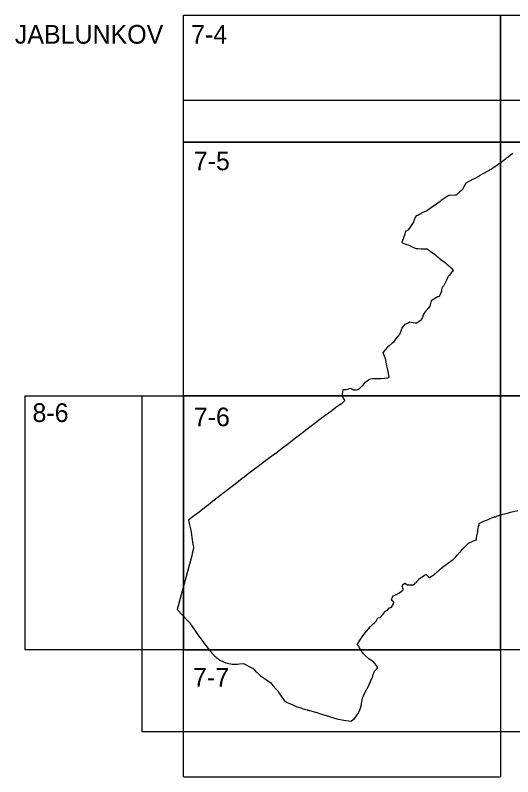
# Model space of a CAD drawing. Extents: x -447352 to -425530, y -1135906 to -1125104.
# Drawn here: x -441800.2 to -441555.1, y -1126653.4 to -1126278.4 of the extents above; entities that cross this region are included whole.
import ezdxf

# ---------------------------------------------------------------- set-up
doc = ezdxf.new("R2010")
doc.units = 0
for name, color, linetype in [('Vrstva 1', 7, 'Continuous'), ('Vrstva 10', 7, 'Continuous'), ('Vrstva 4', 7, 'Continuous')]:
    doc.layers.add(name, color=color, linetype=linetype)

msp = doc.modelspace()

# ---------------------------------------------------------------- linework, layer by layer
at = {"layer": 'Vrstva 1'}
for points in [[(-441555.05, -1126346.44), (-441556.26, -1126347.4), (-441556.26, -1126347.4), (-441557.41, -1126348.27), (-441557.98, -1126348.7), (-441558.56, -1126349.14), (-441558.72, -1126349.26), (-441560.85, -1126350.9), (-441561.92, -1126351.72), (-441562.39, -1126352.06), (-441563.15, -1126352.57), (-441563.4, -1126352.73), (-441563.99, -1126353.12), (-441564.03, -1126353.15), (-441564.24, -1126353.29), (-441565.15, -1126353.89), (-441565.16, -1126353.89), (-441565.63, -1126354.15), (-441565.78, -1126354.23), (-441565.96, -1126354.33), (-441566.42, -1126354.58), (-441566.6, -1126354.69), (-441566.76, -1126354.78), (-441566.86, -1126354.84), (-441567.1, -1126354.98), (-441568.76, -1126355.92), (-441568.93, -1126356.01), (-441569.16, -1126356.14), (-441571.63, -1126357.54), (-441571.75, -1126357.61), (-441573.86, -1126358.74), (-441574.88, -1126359.29), (-441578.22, -1126361.1), (-441578.39, -1126361.4), (-441578.45, -1126361.51), (-441579.23, -1126362.97), (-441579.91, -1126364.29), (-441580.05, -1126364.42), (-441580.14, -1126364.5), (-441581.28, -1126365.54), (-441582.79, -1126366.92), (-441582.96, -1126367.07), (-441582.96, -1126367.08), (-441583.43, -1126367.09), (-441586.62, -1126367.18), (-441586.63, -1126367.18), (-441587.06, -1126367.47), (-441587.89, -1126368.04), (-441590.36, -1126369.7), (-441590.4, -1126369.72), (-441590.64, -1126369.9), (-441590.91, -1126370.1), (-441593.89, -1126372.23), (-441593.96, -1126372.28), (-441596.96, -1126374.46), (-441597.43, -1126374.8), (-441597.59, -1126374.86), (-441599.53, -1126375.58), (-441599.54, -1126375.58), (-441599.93, -1126375.82), (-441601.81, -1126376.98), (-441602.73, -1126377.19), (-441602.98, -1126377.7), (-441603.74, -1126379.21), (-441603.75, -1126379.22), (-441603.82, -1126379.48), (-441604.02, -1126380.32), (-441604.85, -1126381.43), (-441606.22, -1126383.38), (-441606.78, -1126384.19), (-441606.81, -1126384.21), (-441607.97, -1126384.85), (-441608.07, -1126384.91), (-441608.14, -1126385.3), (-441608.29, -1126386.11), (-441608.34, -1126386.3), (-441609.63, -1126389.88), (-441609.8, -1126390.36), (-441609.77, -1126390.35), (-441609.75, -1126390.34), (-441609.07, -1126390.6), (-441607.26, -1126391.26), (-441606.64, -1126391.55), (-441604.35, -1126392.63), (-441604.33, -1126392.63), (-441603.17, -1126393.1), (-441602.7, -1126393.28), (-441602.67, -1126393.29), (-441602.24, -1126393.32), (-441602.1, -1126393.33), (-441601.88, -1126393.35), (-441600.28, -1126393.45), (-441599.24, -1126393.52), (-441598.19, -1126393.49), (-441597.35, -1126393.46), (-441597.34, -1126393.46), (-441597.06, -1126393.61), (-441596.69, -1126393.87), (-441596.14, -1126394.25), (-441595.75, -1126394.53), (-441594.19, -1126395.67), (-441594.02, -1126395.79), (-441592.91, -1126396.71), (-441592.52, -1126397.03), (-441592.34, -1126397.18), (-441591.59, -1126397.79), (-441591.32, -1126398.02), (-441590.72, -1126398.51), (-441590.5, -1126398.69), (-441589.86, -1126399.11), (-441589.11, -1126399.61), (-441589.08, -1126399.63), (-441588.32, -1126400.31), (-441587.44, -1126401.09), (-441587, -1126401.47), (-441585.99, -1126402.36), (-441585.73, -1126402.59), (-441585.68, -1126402.64), (-441585.58, -1126402.74), (-441585.57, -1126402.75), (-441585.48, -1126402.85), (-441585.45, -1126402.88), (-441584.4, -1126404.11), (-441584.41, -1126404.12), (-441584.85, -1126404.61), (-441584.91, -1126404.68), (-441585.48, -1126405.31), (-441586.3, -1126406.37), (-441586.47, -1126406.58), (-441587.03, -1126407.3), (-441587.33, -1126407.83), (-441587.35, -1126407.87), (-441587.36, -1126407.89), (-441587.49, -1126408.17), (-441588.29, -1126409.84), (-441588.6, -1126410.48), (-441589.22, -1126411.77), (-441589.33, -1126412.01), (-441589.34, -1126412.01), (-441589.38, -1126412.04), (-441589.67, -1126412.24), (-441589.75, -1126412.28), (-441589.8, -1126412.38), (-441589.89, -1126412.58), (-441589.98, -1126412.86), (-441590.15, -1126413.42), (-441590.16, -1126413.44), (-441590.28, -1126413.94), (-441590.3, -1126414.01), (-441590.29, -1126414.07), (-441590.28, -1126414.15), (-441590.28, -1126414.22), (-441590.29, -1126414.27), (-441591.17, -1126416.6), (-441591.19, -1126416.65), (-441591.21, -1126416.69), (-441591.22, -1126416.7), (-441591.92, -1126417), (-441592.17, -1126417.11), (-441592.64, -1126417.35), (-441595.25, -1126419.04), (-441595.25, -1126419.04), (-441595.62, -1126420.35), (-441595.7, -1126420.61), (-441595.81, -1126421.03), (-441595.87, -1126421.24), (-441595.87, -1126421.25), (-441595.86, -1126421.25), (-441595.69, -1126421.41), (-441595.7, -1126421.42), (-441596.06, -1126421.81), (-441596.86, -1126422.81), (-441596.87, -1126422.82), (-441597.08, -1126423.07), (-441597.08, -1126423.08), (-441597.2, -1126423.23), (-441598.36, -1126424.58), (-441598.9, -1126425.21), (-441599.66, -1126427.16), (-441600.04, -1126428.18), (-441600.17, -1126428.53), (-441601.7, -1126429.63), (-441602.32, -1126430.07), (-441602.5, -1126430.11), (-441602.52, -1126430.11), (-441603.15, -1126430.02), (-441605.99, -1126429.6), (-441606.48, -1126429.84), (-441607.81, -1126430.48), (-441608.35, -1126430.74), (-441608.38, -1126430.77), (-441608.81, -1126431.18), (-441608.98, -1126431.4), (-441609.64, -1126432.25), (-441609.64, -1126432.26), (-441610.31, -1126434.06), (-441610.88, -1126435.56), (-441610.88, -1126435.56), (-441611.02, -1126435.78), (-441611.35, -1126436.15), (-441612.07, -1126436.95), (-441612.77, -1126437.72), (-441612.78, -1126437.74), (-441612.91, -1126437.93), (-441613.98, -1126439.5), (-441614.45, -1126439.88), (-441616.02, -1126441.14), (-441616.69, -1126441.68), (-441616.79, -1126441.76), (-441616.82, -1126441.8), (-441617.94, -1126443.23), (-441619.08, -1126444.54), (-441618.93, -1126444.71), (-441618.92, -1126444.74), (-441618.92, -1126444.75), (-441617.91, -1126447.51), (-441617.63, -1126449.17), (-441617.31, -1126451.12), (-441616.9, -1126453.08), (-441616.17, -1126456.58), (-441616.13, -1126456.78), (-441616.78, -1126457.12), (-441616.9, -1126457.19), (-441620.07, -1126457.45), (-441620.23, -1126457.45), (-441621.72, -1126457.42), (-441624.11, -1126457.4), (-441625.39, -1126457.67), (-441625.99, -1126457.94), (-441626.97, -1126458.74), (-441628.27, -1126459.61), (-441628.36, -1126459.72), (-441629.52, -1126461.14), (-441630.97, -1126462.48), (-441631.66, -1126462.8), (-441632.26, -1126463.08), (-441633.43, -1126463.01), (-441635.04, -1126462.16), (-441637.28, -1126462.83), (-441638.76, -1126462.8), (-441639.14, -1126464.91), (-441639.15, -1126464.93), (-441639.16, -1126465.02), (-441638.87, -1126466.83), (-441637.9, -1126468.15), (-441637.89, -1126468.17), (-441638.63, -1126468.92), (-441639.24, -1126469.48), (-441639.49, -1126469.71), (-441640.29, -1126470.34), (-441642.22, -1126471.57), (-441642.28, -1126471.61), (-441644.25, -1126473.14), (-441644.31, -1126473.18), (-441644.8, -1126473.56), (-441649.46, -1126477.02), (-441649.49, -1126477.05), (-441654.44, -1126480.81), (-441658.7, -1126484.06), (-441659.58, -1126484.72), (-441662.15, -1126486.66), (-441666.15, -1126489.79), (-441668.59, -1126491.66), (-441671.9, -1126494.19), (-441671.95, -1126494.23), (-441676.74, -1126497.74), (-441676.97, -1126497.92), (-441680.58, -1126500.6), (-441682.97, -1126502.42), (-441684.94, -1126503.9), (-441687.26, -1126505.65), (-441687.49, -1126505.82), (-441688.62, -1126506.71), (-441693.44, -1126510.51), (-441697.33, -1126513.46), (-441701.55, -1126516.71), (-441702.84, -1126517.71), (-441705.23, -1126519.59), (-441706.41, -1126520.51), (-441710.35, -1126523.56), (-441711.28, -1126524.27), (-441712.52, -1126525.23), (-441714.84, -1126527.03), (-441714.84, -1126527.03), (-441714.8, -1126527.21), (-441714.51, -1126528.59), (-441714.48, -1126528.75), (-441713.95, -1126531.29), (-441713.79, -1126532.02), (-441713.79, -1126532.06), (-441712.86, -1126537.94), (-441712.85, -1126537.97), (-441712.55, -1126539.7), (-441712.55, -1126539.72), (-441712.49, -1126540.09), (-441712.43, -1126540.51), (-441712.46, -1126540.88), (-441712.61, -1126541.61), (-441712.99, -1126543.4), (-441713.28, -1126544.58), (-441713.3, -1126544.63), (-441714.41, -1126548.8), (-441716.51, -1126556.68), (-441718.5, -1126563.9), (-441720.43, -1126571), (-441720.44, -1126571.04), (-441715.16, -1126576.64), (-441714.11, -1126577.77), (-441713.35, -1126578.99), (-441711.33, -1126582.05), (-441711.28, -1126582.12), (-441710.27, -1126583.53), (-441710.11, -1126583.74), (-441708.23, -1126586.22), (-441707.66, -1126586.96), (-441707.63, -1126587), (-441707.11, -1126587.72), (-441705.73, -1126589.62), (-441705.4, -1126590.07), (-441703.25, -1126592.79), (-441701.85, -1126594.01), (-441699.45, -1126595.99), (-441697.71, -1126596.74), (-441696.52, -1126597.26), (-441696.39, -1126597.31), (-441695.06, -1126597.59), (-441694.92, -1126597.62), (-441693.3, -1126597.95), (-441693.27, -1126597.95), (-441692.31, -1126597.93), (-441691.93, -1126597.93), (-441691.41, -1126597.92), (-441690.73, -1126597.91), (-441689.82, -1126597.87), (-441687.87, -1126597.71), (-441687.42, -1126597.78), (-441686.76, -1126598.13), (-441685.04, -1126599.08), (-441683.08, -1126600.18), (-441682.56, -1126600.66), (-441681.84, -1126601.34), (-441681.04, -1126602.09), (-441679.72, -1126603.39), (-441679.58, -1126603.49), (-441678.39, -1126604.34), (-441675.98, -1126606.05), (-441674.34, -1126607.23), (-441673.29, -1126608.41), (-441671.65, -1126610.23), (-441671.01, -1126610.94), (-441670.65, -1126611.53), (-441670.19, -1126612.27), (-441669.25, -1126613.74), (-441668.62, -1126614.66), (-441667.58, -1126616.1), (-441666.51, -1126616.61), (-441665.13, -1126617.26), (-441663.82, -1126617.87), (-441661.85, -1126618.76), (-441660.72, -1126619.11), (-441659, -1126619.68), (-441658.85, -1126619.73), (-441657.76, -1126620.05), (-441656.34, -1126620.47), (-441656.33, -1126620.47), (-441656.12, -1126620.53), (-441656.06, -1126620.55), (-441655.2, -1126620.81), (-441652.81, -1126621.5), (-441652.69, -1126621.54), (-441652.21, -1126621.68), (-441649.28, -1126622.55), (-441646.59, -1126623.38), (-441646.25, -1126623.48), (-441645.49, -1126623.71), (-441643.48, -1126624.33), (-441641.75, -1126624.88), (-441638.29, -1126625.62)], [(-441638.29, -1126625.62), (-441635.9, -1126625.81), (-441634.7, -1126626.04), (-441634.59, -1126625.95), (-441633.01, -1126624.68), (-441631.98, -1126623.2), (-441631.87, -1126623.05), (-441631.35, -1126622.29), (-441631.24, -1126622.12), (-441631.1, -1126621.89), (-441630.72, -1126621.26), (-441630.45, -1126620.43), (-441630.43, -1126620.36), (-441630.41, -1126620.31), (-441630.38, -1126620.2), (-441630.35, -1126620.11), (-441630.35, -1126620.1), (-441629.72, -1126617.9), (-441629.58, -1126617.38), (-441629.13, -1126614.63), (-441629.13, -1126614.63), (-441628.94, -1126614.19), (-441628.68, -1126613.57), (-441627.89, -1126611.74), (-441626.32, -1126609.09), (-441624.57, -1126604.96), (-441624.25, -1126604.32), (-441624.21, -1126604.19), (-441623.82, -1126603.09), (-441623.23, -1126601.42), (-441621.55, -1126599.71), (-441622.48, -1126598.47), (-441622.54, -1126598.38), (-441622.59, -1126598.32), (-441622.62, -1126598.28), (-441622.69, -1126598.18), (-441622.74, -1126598.1), (-441622.82, -1126597.98), (-441623.18, -1126597.46), (-441623.55, -1126597), (-441624.12, -1126596.63), (-441624.22, -1126596.57), (-441625.87, -1126595.5), (-441628.06, -1126593.56), (-441628.19, -1126593.39), (-441628.22, -1126593.35), (-441628.3, -1126593.25), (-441628.64, -1126592.83), (-441628.97, -1126592.42), (-441629.23, -1126592.1), (-441629.71, -1126591.51), (-441629.79, -1126591.41), (-441630.29, -1126590.45), (-441630.58, -1126589.89), (-441630.81, -1126589.46), (-441630.86, -1126589.37), (-441630.9, -1126589.32), (-441631.16, -1126589.03), (-441631.36, -1126588.8), (-441631.62, -1126588.51), (-441631.84, -1126588.26), (-441629.98, -1126585.52), (-441629.89, -1126585.4), (-441629.57, -1126584.95), (-441629.25, -1126584.51), (-441627.92, -1126582.68), (-441625.24, -1126579.42), (-441624.89, -1126579.1), (-441624.18, -1126578.4), (-441624.07, -1126578.31), (-441623.88, -1126578.17), (-441623.28, -1126577.69), (-441622.42, -1126576.85), (-441622.01, -1126576.09), (-441621.54, -1126575.22), (-441620.49, -1126574.98), (-441619.09, -1126573.55), (-441618.55, -1126572.7), (-441618.54, -1126572.69), (-441618.54, -1126572.67), (-441618.33, -1126572.34), (-441618.28, -1126572.26), (-441618.04, -1126571.87), (-441616.88, -1126571.43), (-441615.86, -1126570.25), (-441615.33, -1126570.05), (-441615.21, -1126570), (-441614.79, -1126569.84), (-441614.57, -1126569.45), (-441614.52, -1126569.36), (-441614.35, -1126569.06), (-441613.94, -1126568.32), (-441613.74, -1126567.41), (-441613.74, -1126567.39), (-441613.73, -1126567.38), (-441614.78, -1126566.39), (-441614.8, -1126566.38), (-441614.81, -1126566.36), (-441614.86, -1126566.32), (-441614.21, -1126564.52), (-441614.14, -1126564.32), (-441613.98, -1126564.26), (-441613.25, -1126563.97), (-441612.56, -1126563.7), (-441612.44, -1126563.65), (-441611.23, -1126562.94), (-441611.11, -1126562.86), (-441611.11, -1126562.86), (-441611.1, -1126562.85), (-441610.98, -1126562.78), (-441609.12, -1126561.38), (-441609.12, -1126561.34), (-441609.15, -1126561.18), (-441609.22, -1126560.7), (-441609.28, -1126560.35), (-441609.38, -1126559.73), (-441609.4, -1126559.62), (-441609.42, -1126559.49), (-441609.44, -1126559.32), (-441609.47, -1126559.18), (-441608.93, -1126558.62), (-441608.37, -1126558.05), (-441608.33, -1126558), (-441608.19, -1126558.1), (-441607.19, -1126558.89), (-441606.51, -1126558.9), (-441606.45, -1126558.9), (-441606.2, -1126558.91), (-441606.04, -1126558.91), (-441604.73, -1126558.93), (-441604.1, -1126558.95), (-441603.83, -1126558.79), (-441603.8, -1126558.77), (-441603.68, -1126558.7), (-441603.54, -1126558.61), (-441603.5, -1126558.58), (-441602.96, -1126557.98), (-441602.85, -1126557.86), (-441602.76, -1126557.76), (-441602.59, -1126557.58), (-441602.51, -1126557.49), (-441602.4, -1126557.37), (-441602.37, -1126557.33), (-441602.34, -1126557.3), (-441602.29, -1126557.24), (-441602.2, -1126557.13), (-441601.8, -1126556.63), (-441601.59, -1126556.37), (-441601.34, -1126556.05), (-441601.23, -1126555.97), (-441599.77, -1126554.9), (-441599.56, -1126554.77), (-441598.2, -1126554), (-441597.8, -1126553.77), (-441597.8, -1126553.77), (-441597.66, -1126553.92), (-441596.95, -1126554.63), (-441596.58, -1126555.01), (-441596.4, -1126555.18), (-441596.25, -1126555.33), (-441596.16, -1126555.29), (-441594.88, -1126554.52), (-441594.79, -1126554.47), (-441593.86, -1126553.91), (-441593.82, -1126553.88), (-441593.49, -1126553.59), (-441593.44, -1126553.55), (-441593.27, -1126553.4), (-441593.26, -1126553.39), (-441593.26, -1126553.39), (-441593.22, -1126553.35), (-441593.18, -1126553.31), (-441592.29, -1126552.5), (-441592.27, -1126552.49), (-441591.68, -1126551.95), (-441591.57, -1126551.86), (-441591.46, -1126551.76), (-441591.46, -1126551.76), (-441591.45, -1126551.76), (-441591.45, -1126551.76), (-441591.45, -1126551.75), (-441591.44, -1126551.75), (-441591.43, -1126551.74), (-441591.43, -1126551.74), (-441591.42, -1126551.73), (-441591.42, -1126551.73), (-441591.41, -1126551.73), (-441591.41, -1126551.73), (-441590.83, -1126551.24), (-441588.84, -1126549.56), (-441587.64, -1126548.71), (-441587.52, -1126548.63), (-441587.47, -1126548.59), (-441587.45, -1126548.58), (-441587.4, -1126548.55), (-441587.04, -1126548.28), (-441585.8, -1126547.34), (-441585.62, -1126547.2), (-441585.41, -1126547.04), (-441585.39, -1126547.02), (-441584.51, -1126546.35), (-441584.16, -1126546.08), (-441584.11, -1126546.02), (-441584.02, -1126545.92), (-441583.38, -1126545.24), (-441582.48, -1126544.26), (-441581.12, -1126542.85), (-441580.9, -1126542.62), (-441580.65, -1126542.34), (-441579.81, -1126541.39), (-441579.52, -1126541.07), (-441579.32, -1126540.86), (-441579.03, -1126540.54), (-441577.85, -1126539.35), (-441576.92, -1126538.33), (-441574.86, -1126537.32), (-441574.7, -1126537.27), (-441574.5, -1126537.19), (-441573.06, -1126536.7), (-441572.91, -1126535.83), (-441572.75, -1126534.96), (-441572.33, -1126532.59), (-441572.25, -1126532.12), (-441571.92, -1126530.24), (-441571.72, -1126529.36), (-441571.69, -1126529.24), (-441571.64, -1126529.05), (-441571.63, -1126529.01), (-441571.61, -1126528.94), (-441571.6, -1126528.9), (-441571.59, -1126528.85), (-441571.58, -1126528.81), (-441571.57, -1126528.79), (-441571.51, -1126528.58), (-441570.43, -1126528.04), (-441570.14, -1126527.9), (-441570.12, -1126527.89), (-441569.87, -1126527.76), (-441569.82, -1126527.74), (-441568.05, -1126527.02), (-441568.02, -1126527.01), (-441567.99, -1126526.99), (-441567.19, -1126526.68), (-441566.23, -1126526.28), (-441565.42, -1126525.94), (-441564.48, -1126525.55), (-441564.4, -1126525.52), (-441563.79, -1126525.28), (-441563.94, -1126525.44), (-441563.7, -1126525.35), (-441563.21, -1126525.15), (-441562.68, -1126524.99), (-441560.98, -1126524.47), (-441560.39, -1126524.3), (-441559.94, -1126524.18), (-441559.05, -1126523.93), (-441557.74, -1126523.55), (-441556.2, -1126523.09), (-441552.66, -1126522.22)]]:
    msp.add_lwpolyline(points, dxfattribs=at)
at = {"layer": 'Vrstva 10'}
msp.add_lwpolyline([(-441404.9, -1126320.23), (-441404.9, -1126631.21), (-441737.77, -1126631.21), (-441737.77, -1126465.91), (-441717.4, -1126465.91), (-441717.4, -1126340.91), (-441717.4, -1126320.23), (-441404.9, -1126320.23)], dxfattribs=at)
at = {"layer": 'Vrstva 4'}
for p, q in [((-441717.4, -1126278.41), (-441404.9, -1126278.41)), ((-441795.53, -1126465.91), (-441795.53, -1126590.91)), ((-441717.4, -1126653.41), (-441561.15, -1126653.41))]:
    msp.add_line(p, q, dxfattribs=at)
for points in [[(-441561.15, -1126278.41), (-441561.15, -1126340.91), (-441717.4, -1126340.91), (-441717.4, -1126278.41)], [(-441404.9, -1126278.41), (-441404.9, -1126340.91), (-441561.15, -1126340.91), (-441561.15, -1126278.41)], [(-441795.53, -1126465.91), (-441717.4, -1126465.91), (-441717.4, -1126590.91), (-441795.53, -1126590.91)], [(-441717.4, -1126653.41), (-441717.4, -1126590.91), (-441561.15, -1126590.91), (-441561.15, -1126653.41)]]:
    msp.add_lwpolyline(points, dxfattribs=at)
for points in [[(-441561.15, -1126340.91), (-441561.15, -1126465.91), (-441717.4, -1126465.91), (-441717.4, -1126340.91)], [(-441404.9, -1126340.91), (-441404.9, -1126465.91), (-441561.15, -1126465.91), (-441561.15, -1126340.91)], [(-441561.15, -1126465.91), (-441561.15, -1126590.91), (-441717.4, -1126590.91), (-441717.4, -1126465.91)], [(-441404.9, -1126465.91), (-441404.9, -1126590.91), (-441561.15, -1126590.91), (-441561.15, -1126465.91)]]:
    msp.add_lwpolyline(points, close=True, dxfattribs=at)

# ---------------------------------------------------------------- texts
at = {"layer": 'Vrstva 1'}
for s, p in [('JABLUNKOV', (-441800.44, -1126292.41)), ('7-4', (-441713.59, -1126292.41)), ('7-5', (-441712.28, -1126354.75)), ('8-6', (-441791.75, -1126478.72)), ('7-6', (-441712.28, -1126480.82)), ('7-7', (-441712.64, -1126608.99))]:
    msp.add_text(s, height=9.2, dxfattribs=at).set_placement(p)

doc.saveas('drawing.dxf')
